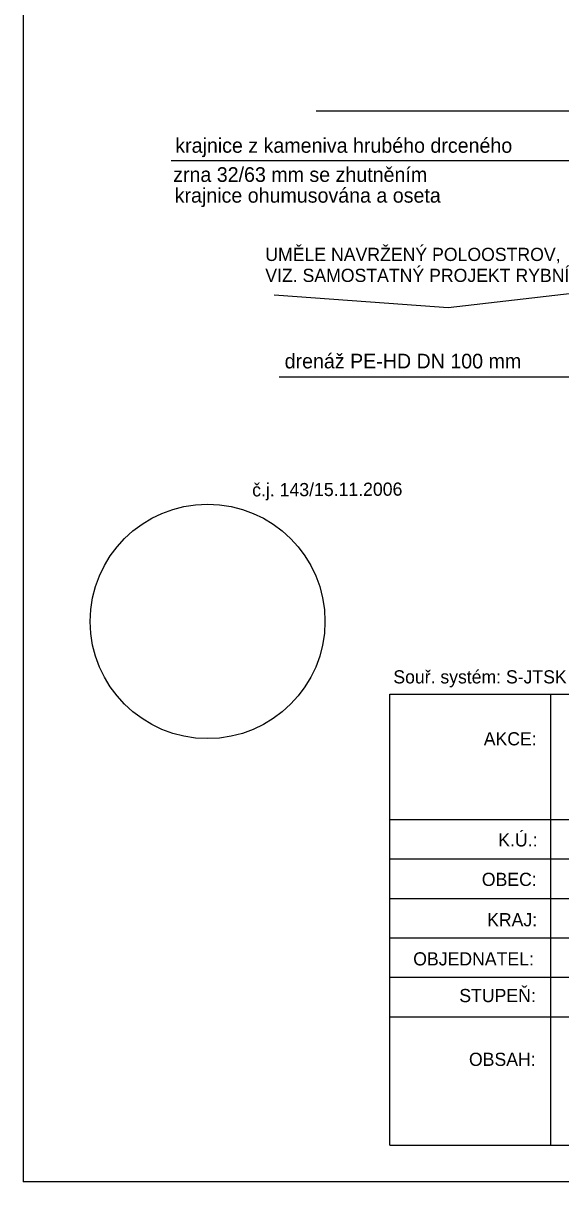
# Model space of a CAD drawing. Extents: x -553158.6 to -553137.6, y -1027695 to -1027665.3.
# Drawn here: x -553158.61 to -553151.28, y -1027695.04 to -1027679.22 of the extents above; entities that cross this region are included whole.
import ezdxf

# ---------------------------------------------------------------- set-up
doc = ezdxf.new("R2010")
doc.units = 0
for name, color, linetype in [('16', 7, 'Continuous'), ('Implicitní', 7, 'Continuous'), ('POPIS', 7, 'Continuous'), ('rámeček', 7, 'Continuous')]:
    doc.layers.add(name, color=color, linetype=linetype)

# ---------------------------------------------------------------- blocks, each defined once
blk = doc.blocks.new('A$C038E1F8A')
at = {"layer": 'Implicitní'}
for p in [(-0.21, 0.297), (0, 0)]:
    blk.add_line(p, (-0.21, 0), dxfattribs=at)

msp = doc.modelspace()

# ---------------------------------------------------------------- linework, layer by layer
msp.add_line((-553150.878, -1027680.424), (-553154.614, -1027680.424))
msp.add_lwpolyline([(-553155.188, -1027682.933), (-553153.625, -1027683.047), (-553152.816, -1027683.106), (-553151.128, -1027682.91), (-553151.063, -1027682.901), (-553150.844, -1027682.897), (-553150.384, -1027682.888), (-553149.19, -1027682.863), (-553147.44, -1027682.863), (-553146.554, -1027682.857), (-553145.643, -1027682.939), (-553143.976, -1027683.087), (-553143.187, -1027683.272), (-553142.31, -1027683.379), (-553141.188, -1027683.464)])
at = {"layer": 'POPIS'}
for p, q in [((-553150.249, -1027681.105), (-553156.595, -1027681.105)), ((-553155.12, -1027684.053), (-553149.889, -1027684.053))]:
    msp.add_line(p, q, dxfattribs=at)
at = {"layer": 'rámeček'}
for p, q in [((-553153.611, -1027688.383), (-553138.111, -1027688.383)), ((-553153.611, -1027694.538), (-553153.611, -1027688.383)), ((-553151.418, -1027694.538), (-553151.418, -1027688.383)), ((-553153.611, -1027690.091), (-553138.111, -1027690.091)), ((-553153.611, -1027690.63), (-553138.111, -1027690.63)), ((-553153.611, -1027691.169), (-553138.111, -1027691.169)), ((-553153.611, -1027691.708), (-553138.111, -1027691.708)), ((-553153.611, -1027692.247), (-553138.111, -1027692.247)), ((-553153.611, -1027692.786), (-553139.6, -1027692.786)), ((-553153.611, -1027694.538), (-553138.111, -1027694.538))]:
    msp.add_line(p, q, dxfattribs=at)
msp.add_circle((-553156.096, -1027687.389), 1.6, dxfattribs=at)

# ---------------------------------------------------------------- block references
at = {"layer": 'Implicitní', "xscale": 100, "yscale": 100}
msp.add_blockref('A$C038E1F8A', (-553137.611, -1027695.038), dxfattribs=at)

# ---------------------------------------------------------------- texts
at = {"layer": '16'}
for s, p in [('UMĚLE NAVRŽENÝ POLOOSTROV,', (-553155.31, -1027682.47)), ('VIZ. SAMOSTATNÝ PROJEKT RYBNÍKA', (-553155.31, -1027682.756))]:
    msp.add_text(s, height=0.18, dxfattribs=at).set_placement(p)
at = {"layer": 'POPIS'}
for s, p in [('krajnice z kameniva hrubého drceného', (-553156.537, -1027680.993)), ('zrna 32/63 mm se zhutněním', (-553156.566, -1027681.39)), ('krajnice ohumusována a oseta', (-553156.545, -1027681.674)), ('drenáž PE-HD DN 100 mm', (-553155.046, -1027683.936))]:
    msp.add_text(s, height=0.2, dxfattribs=at).set_placement(p)
at = {"layer": 'rámeček'}
for s, height, rotation, p in [('č.j. 143/15.11.2006', 0.18, 0.3084, (-553155.488, -1027685.684)), ('Souř. systém: S-JTSK', 0.17971, 0, (-553153.564, -1027688.236)), ('AKCE:', 0.1797, 0, (-553152.331, -1027689.081)), ('K.Ú.:', 0.18, 0, (-553152.134, -1027690.461)), ('OBEC:', 0.18, 0, (-553152.358, -1027691)), ('KRAJ:', 0.18, 0, (-553152.286, -1027691.551)), ('OBJEDNATEL:', 0.18, 0, (-553153.293, -1027692.085)), ('STUPEŇ:', 0.18, 0, (-553152.665, -1027692.586)), ('OBSAH:', 0.18, 0, (-553152.533, -1027693.456))]:
    msp.add_text(s, height=height, rotation=rotation, dxfattribs=at).set_placement(p)

doc.saveas('drawing.dxf')
